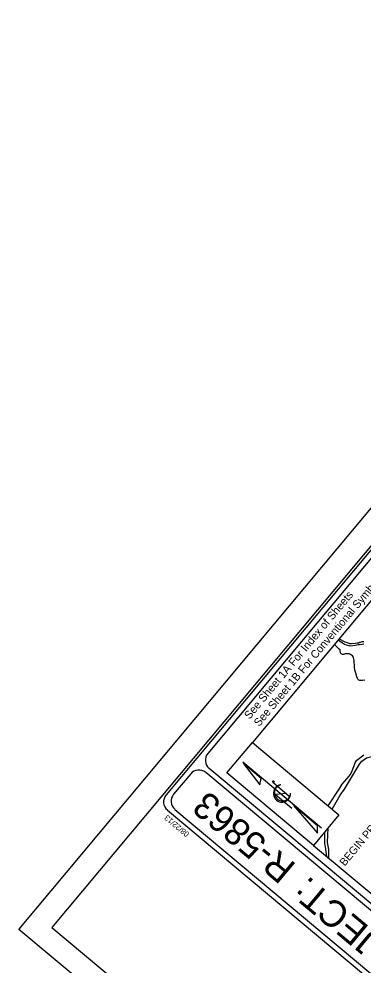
# Model space of a CAD drawing. Extents: x 555292 to 2368606, y 503623 to 1171444.
# Drawn here: x 2355032 to 2356645, y 1162339 to 1166770 of the extents above; entities that cross this region are included whole.
import ezdxf

# ---------------------------------------------------------------- set-up
doc = ezdxf.new("R2010")
doc.units = 0
for name, color, linetype in [('Old_Level_1', 7, 'Continuous'), ('Old_Level_22', 7, 'Continuous'), ('Old_Level_32', 7, 'Continuous'), ('Old_Level_59', 7, 'Continuous'), ('Old_Level_60', 7, 'Continuous'), ('Sheet Cutting Line CELL', 7, 'Continuous'), ('Sheet Plot Border Inside CELL', 7, 'Continuous'), ('Sheet Plot Border Outside CELL', 7, 'Continuous'), ('Sheet Title CELL', 7, 'Continuous')]:
    doc.layers.add(name, color=color, linetype=linetype)

msp = doc.modelspace()

# ---------------------------------------------------------------- linework, layer by layer
at = {"layer": 'Old_Level_1'}
for p, q in [((2357074.9, 1164516.4), (2356126.1, 1163382.1)), ((2356450.7, 1162981), (2356081.7, 1163289.6)), ((2356221.7, 1163196.1), (2356297.4, 1163132.8)), ((2356258.7, 1163183), (2356259.3, 1163183.1)), ((2356285.6, 1163142.7), (2356233.8, 1163138)), ((2356233.8, 1163138), (2356310.8, 1163073.6)), ((2356412.4, 1162899.9), (2357068.1, 1162351.5))]:
    msp.add_line(p, q, dxfattribs=at)
for points in [[(2356006.7, 1163239.3), (2356126.1, 1163382.1), (2356531.9, 1163042.7), (2356412.4, 1162899.9)], [(2356082.8, 1163284.4), (2356161, 1163183.1), (2356167.9, 1163213.1)], [(2356318.2, 1163086.7), (2356430.7, 1162957.1), (2356431.7, 1162991.7)]]:
    msp.add_lwpolyline(points, close=True, dxfattribs=at)
msp.add_lwpolyline([(2356126.1, 1163382.1), (2356531.9, 1163042.7), (2356412.4, 1162899.9)], dxfattribs=at)
msp.add_circle((2356224.3, 1163199.1), 3.92, dxfattribs=at)
for centre, radius, start, end in [((2356264.8, 1163143.1), 40.4, 97.9297, 2.4838), ((2356267.3, 1163146.1), 37.9, 103.1847, 358.7184)]:
    msp.add_arc(centre, radius, start, end, dxfattribs=at)
at = {"layer": 'Old_Level_32'}
for points in [[(2356652.8, 1163673.1), (2356642.6, 1163671.9), (2356630.1, 1163672.2), (2356625.5, 1163673.7), (2356623, 1163675.3), (2356620.2, 1163678.2), (2356618.2, 1163681.7), (2356615.7, 1163689.4), (2356610.5, 1163706.3), (2356606.7, 1163720.2), (2356604.8, 1163736.9), (2356602.5, 1163765), (2356600, 1163779.8), (2356599.1, 1163781.7), (2356594.8, 1163787.1), (2356590.3, 1163791.4), (2356585.7, 1163794.3), (2356579.1, 1163796.4), (2356570.5, 1163797.3), (2356562.3, 1163796.3), (2356552.9, 1163794.2), (2356547.6, 1163794.2), (2356545.1, 1163794.8), (2356542.3, 1163796.7), (2356540.5, 1163798.9), (2356539.5, 1163801.6), (2356538, 1163811.8), (2356536.8, 1163815.2), (2356532.8, 1163819.5), (2356510.4, 1163841.5)], [(2356481.9, 1163084.5), (2356533.2, 1163162.8), (2356546.8, 1163186.9), (2356579, 1163223.4), (2356583.9, 1163230.1), (2356589.8, 1163241.2), (2356601.7, 1163268.7), (2356609.9, 1163290), (2356616, 1163299.1), (2356648.1, 1163324)], [(2356475, 1162847.6), (2356468, 1162893.1), (2356466.1, 1162909.1), (2356465.5, 1162963.4)]]:
    msp.add_lwpolyline(points, dxfattribs=at)
at = {"layer": 'Old_Level_59'}
for points in [[(2356500, 1163069.3), (2356537.5, 1163135.7), (2356558.1, 1163163.2), (2356627.5, 1163280.4), (2356639.3, 1163294.5), (2356661.2, 1163310.5), (2356722, 1163325.9), (2356763.2, 1163354.7), (2356775.8, 1163377.1), (2356767, 1163496.3), (2356809.8, 1163601.8), (2356820.8, 1163637), (2356847.4, 1163705.4), (2356838.5, 1163768), (2356842.3, 1163781.4)], [(2356484.5, 1162839.6), (2356484.1, 1162881.3), (2356478.2, 1162912.8), (2356481, 1162981.9)]]:
    msp.add_lwpolyline(points, dxfattribs=at)
at = {"layer": 'Old_Level_60'}
for points in [[(2356528.4, 1163863), (2356549.1, 1163848.8), (2356558.3, 1163842.2), (2356564.9, 1163839.6), (2356571.5, 1163838.2)], [(2356532.5, 1163868), (2356558.5, 1163854), (2356569.5, 1163849.9), (2356581.4, 1163846.2), (2356591.2, 1163846.2), (2356606.9, 1163847.7), (2356617.2, 1163848.3), (2356623.3, 1163849.3), (2356628.1, 1163850.9), (2356632.4, 1163851.5), (2356642.8, 1163855.1), (2356649, 1163854.3)], [(2356571.5, 1163838.2), (2356577.7, 1163835.7), (2356583.4, 1163834.8), (2356597.1, 1163836.2), (2356609, 1163837.7), (2356621.6, 1163840.6), (2356628.2, 1163840), (2356640.8, 1163842.7), (2356648.1, 1163843.6)]]:
    msp.add_lwpolyline(points, dxfattribs=at)
at = {"layer": 'Sheet Cutting Line CELL'}
msp.add_line((2355032.5, 1162506.7), (2360434.7, 1168965.2), dxfattribs=at)
at = {"layer": 'Sheet Plot Border Inside CELL'}
msp.add_lwpolyline([(2359232.5, 1159130.5), (2364578.6, 1165521.9), (2360532, 1168906.6), (2355185.9, 1162515.2)], close=True, dxfattribs=at)
at = {"layer": 'Sheet Plot Border Outside CELL'}
for p, q in [((2355032.5, 1162506.7), (2360486, 1169026.6)), ((2359251.2, 1158978), (2355032.5, 1162506.7))]:
    msp.add_line(p, q, dxfattribs=at)
at = {"layer": 'Sheet Title CELL'}
for p, q in [((2359819.6, 1159969.2), (2355907.6, 1163241.3)), ((2359126.1, 1160581.9), (2355923.7, 1163260.5))]:
    msp.add_line(p, q, dxfattribs=at)
for points in [[(2360469.6, 1168812.2), (2355721.7, 1163136)], [(2360472.7, 1168777), (2355917.5, 1163331)], [(2360472.7, 1168777), (2355917.5, 1163331)], [(2355837.2, 1163235), (2355757, 1163139.2)], [(2355728.1, 1163065.6), (2359678.3, 1159761.4)], [(2355728.1, 1163065.6), (2359678.3, 1159761.4)], [(2355763.3, 1163068.8), (2359675.2, 1159796.7)]]:
    msp.add_lwpolyline(points, dxfattribs=at)
for centre, start, end in [((2355955.6, 1163299), 140.0895, 230.0895), ((2355875.4, 1163203.2), 50.0895, 140.0895), ((2355760, 1163104.1), 140.0895, 230.0895), ((2355795.2, 1163107.3), 140.0895, 230.0895)]:
    msp.add_arc(centre, 50, start, end, dxfattribs=at)

# ---------------------------------------------------------------- texts
at = {"layer": 'Old_Level_22'}
msp.add_text('BEGIN PROJECT', height=36.575, rotation=50.2196, dxfattribs=at).set_placement((2356559, 1162800.2))
at = {"layer": 'Sheet Title CELL'}
for s, height, rotation, p in [('See Sheet 1B For Conventional Symbols', 37.5, 50.0895, (2356157.9, 1163453.7)), ('See Sheet 1A For Index of Sheets', 37.5, 50.0895, (2356112.9, 1163487.9)), ('R-5863', 125, 140.0895, (2356336.4, 1162808.5)), ('08/22/13', 26.25, 140.0895, (2355832.7, 1162956.9)), ('PROJECT:', 125, 140.0895, (2357020.1, 1162230.5))]:
    msp.add_text(s, height=height, rotation=rotation, dxfattribs=at).set_placement(p)

doc.saveas('drawing.dxf')
